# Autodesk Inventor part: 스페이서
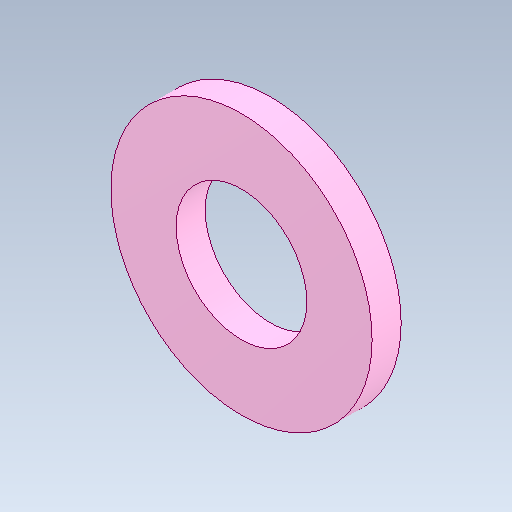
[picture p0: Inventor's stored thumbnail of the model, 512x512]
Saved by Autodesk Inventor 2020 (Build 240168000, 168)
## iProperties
Created: 2024-04
Part Number: 스페이서
Material: 강철, 연강
Document SubType Name: Modeling
Designer: oem
Density: 7.86 g/cm^3
Appearance: 기본값
Mass: 3.00019 g
Surface Area: 5.5135 cm^2
Volume: 0.381704 cm^3
Sending System: Autodesk Inventor 2025
Preprocessor: ST-DEVELOPER v20
Author: jhkim
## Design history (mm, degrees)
feature "솔리드1"
node "솔리드2"
